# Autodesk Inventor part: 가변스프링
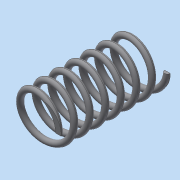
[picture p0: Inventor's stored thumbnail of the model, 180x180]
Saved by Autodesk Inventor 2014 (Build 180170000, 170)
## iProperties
Created: 2021-08
Part Number: 가변스프링
Material: 일반
Document SubType Name: Modeling
Designer: dg
Density: 1 g/cm^3
Appearance: 기본값
Mass: 1.09305 g
Surface Area: 22.123 cm^2
Volume: 1.09305 cm^3
Author: dg
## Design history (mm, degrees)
sketch "스케치1"
  geometry: L1 (8, 0)-(0, 0); L2 (0, 0)-(0, 38); L3 (0, 38)-(8, 38); C1 r 1 at (8, 0)
  constraints: 6 end point, 1 centre point, 1 coincident, 1 horizontal, 1 parallel, 1 perpendicular, 1 vertical alignment
  dimensions: "d0" = 16 diameter of L1.start L2; "d1" = 2 diameter of C1; "d2" = 38 distance of L1.end L2.end (derived)
feature "코일1" sketch "스케치1" pitch "d3" = 10; turns "d5" = 7; dims "d4" = 38 (= d2), "d6" = 0, angle "d7" = 90 deg, angle "d8" = 90 deg, "d9" = 0, "d10" = 0
node "작업 평면1"
feature "분할1"
feature "분할2"
node "솔리드1"
other parameters: "d11" = 0
